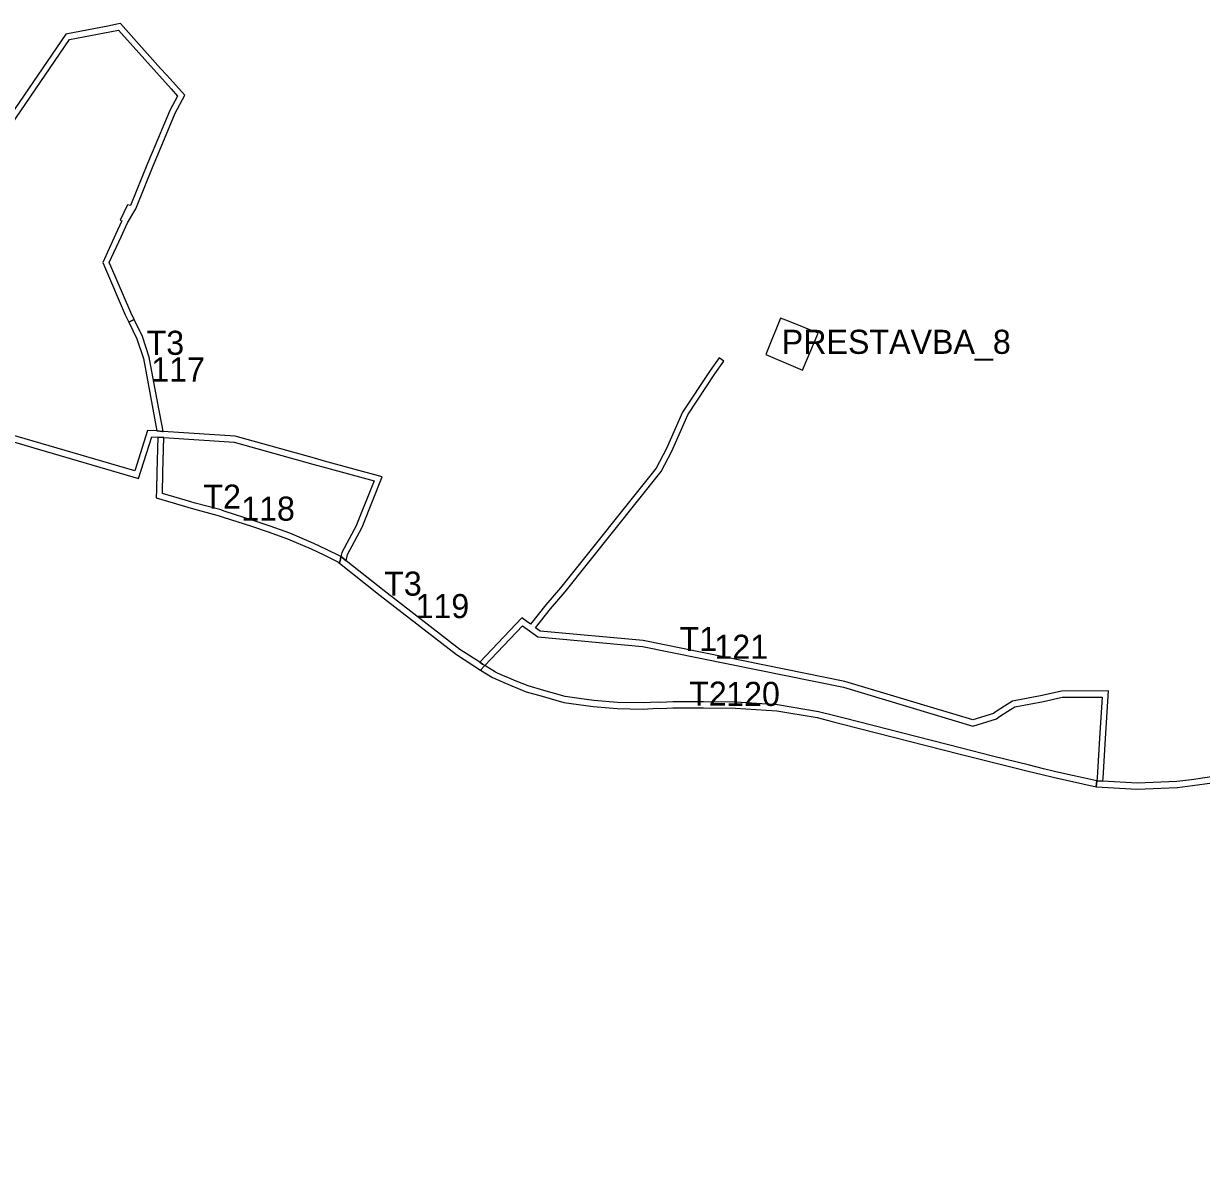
# Model space of a CAD drawing. Extents: x -477001 to -465642, y -1158278 to -1150672.
# Drawn here: x -471244 to -470657, y -1153956 to -1153393 of the extents above; entities that cross this region are included whole.
import ezdxf

# ---------------------------------------------------------------- set-up
doc = ezdxf.new("R2010")
doc.units = 0
for name, color, linetype in [('prestavba_n', 7, 'Continuous'), ('VPS_id', 7, 'Continuous'), ('VPS_n', 7, 'Continuous'), ('vyvlastneni_n', 7, 'Continuous')]:
    doc.layers.add(name, color=color, linetype=linetype)

msp = doc.modelspace()

# ---------------------------------------------------------------- linework, layer by layer
at = {"layer": 'prestavba_n'}
for p, q in [((-470866.99, -1153540.14), (-470869.35, -1153545.96)), ((-470863.08, -1153541.69), (-470866.99, -1153540.14)), ((-470848.29, -1153547.56), (-470863.08, -1153541.69)), ((-470870.6, -1153549.05), (-470874.35, -1153558.31)), ((-470869.35, -1153545.96), (-470870.6, -1153549.05)), ((-470856.01, -1153566.04), (-470848.29, -1153547.56)), ((-470874.35, -1153558.31), (-470856.01, -1153566.04))]:
    msp.add_line(p, q, dxfattribs=at)
at = {"layer": 'VPS_n'}
for p, q in [((-471192.58, -1153492.66), (-471188.38, -1153485.63)), ((-471195.38, -1153491.58), (-471198.48, -1153498.37)), ((-471195.75, -1153499.62), (-471192.58, -1153492.66)), ((-471191.89, -1153542.05), (-471189.19, -1153540.74)), ((-471189.19, -1153540.74), (-471191.89, -1153542.05)), ((-471191.89, -1153542.05), (-471187.8, -1153550.48)), ((-470895.17, -1153561.57), (-470897.61, -1153559.82)), ((-471175.31, -1153593.86), (-471176.89, -1153585.31)), ((-471182.54, -1153596.05), (-471188.94, -1153616.26)), ((-471177.9, -1153596.35), (-471175, -1153596.54)), ((-471174.82, -1153596.56), (-471175.31, -1153593.86)), ((-471175, -1153596.54), (-471174.82, -1153596.56)), ((-471180.39, -1153599.2), (-471177.37, -1153599.39)), ((-471177.37, -1153599.39), (-471174.38, -1153599.59)), ((-471174.38, -1153599.59), (-471177.37, -1153599.39)), ((-471174.96, -1153617.12), (-471174.38, -1153599.59)), ((-471174.38, -1153599.59), (-471139.38, -1153601.89)), ((-471175.11, -1153627.46), (-471174.96, -1153617.12)), ((-471178.26, -1153629.66), (-471159.57, -1153635.15)), ((-471086.84, -1153662.19), (-471086.38, -1153660.19)), ((-471086.38, -1153660.19), (-471086.84, -1153662.19)), ((-471086.38, -1153660.19), (-471086.1, -1153658.95)), ((-471086.1, -1153658.95), (-471086.38, -1153660.19)), ((-471085.63, -1153659.32), (-471086.1, -1153658.95)), ((-471083.49, -1153661.02), (-471085.63, -1153659.32)), ((-470995.98, -1153689.49), (-471016.95, -1153711.63)), ((-470991.57, -1153692.66), (-470995.98, -1153689.49)), ((-471016.95, -1153711.63), (-471026.84, -1153705.29)), ((-471016.48, -1153715.49), (-471014.38, -1153713.28)), ((-471014.38, -1153713.28), (-471016.48, -1153715.49)), ((-471009.13, -1153716.64), (-471014.38, -1153713.28)), ((-471005.94, -1153717.99), (-471009.13, -1153716.64)), ((-471003.71, -1153718.93), (-471005.94, -1153717.99)), ((-471004.87, -1153721.7), (-470993.83, -1153726.29)), ((-470984.95, -1153725.7), (-470992.84, -1153723.45)), ((-470974.36, -1153728.66), (-470984.95, -1153725.7)), ((-470948.27, -1153731.66), (-470960, -1153730.73)), ((-470926.6, -1153731.66), (-470928.14, -1153731.46)), ((-470920.74, -1153731.36), (-470926.6, -1153731.66)), ((-470889.3, -1153731.56), (-470905.33, -1153731.41)), ((-470868.42, -1153732.82), (-470889.3, -1153731.56)), ((-470967.77, -1153732.64), (-470960.33, -1153733.71)), ((-470960.33, -1153733.71), (-470948.42, -1153734.66)), ((-470948.42, -1153734.66), (-470935.44, -1153734.92)), ((-470935.44, -1153734.92), (-470928.24, -1153734.47)), ((-470928.24, -1153734.47), (-470926.72, -1153734.67)), ((-470926.72, -1153734.67), (-470920.67, -1153734.36)), ((-470920.67, -1153734.36), (-470905.35, -1153734.41)), ((-470905.35, -1153734.41), (-470889.4, -1153734.56)), ((-470889.4, -1153734.56), (-470868.76, -1153735.8)), ((-470868.76, -1153735.8), (-470848.75, -1153739.2)), ((-470848.12, -1153736.26), (-470868.42, -1153732.82)), ((-470840.51, -1153738.22), (-470848.12, -1153736.26)), ((-470835.3, -1153739.56), (-470840.51, -1153738.22)), ((-470776.74, -1153754.52), (-470835.3, -1153739.56)), ((-470761.34, -1153758.41), (-470776.74, -1153754.52)), ((-470762.07, -1153761.32), (-470743.52, -1153765.87)), ((-470742.81, -1153762.96), (-470761.34, -1153758.41)), ((-470735.83, -1153764.66), (-470742.81, -1153762.96)), ((-470730.43, -1153766.03), (-470735.83, -1153764.66)), ((-470728.24, -1153766.52), (-470730.43, -1153766.03)), ((-470709.29, -1153770.76), (-470728.24, -1153766.52)), ((-470709.71, -1153773.74), (-470709.29, -1153770.76)), ((-470709.29, -1153770.76), (-470709.71, -1153773.74)), ((-470709.29, -1153770.76), (-470706.29, -1153770.93)), ((-470706.29, -1153770.93), (-470709.29, -1153770.76)), ((-470706.29, -1153770.93), (-470706.28, -1153770.75)), ((-470689.26, -1153771.93), (-470706.29, -1153770.93)), ((-470669.37, -1153771.05), (-470689.26, -1153771.93)), ((-470662.1, -1153770.15), (-470669.37, -1153771.05)), ((-470652.22, -1153768.74), (-470662.1, -1153770.15)), ((-470709.71, -1153773.74), (-470689.28, -1153774.93)), ((-470689.28, -1153774.93), (-470669.24, -1153774.05)), ((-470669.24, -1153774.05), (-470669.12, -1153774.05))]:
    msp.add_line(p, q, dxfattribs=at)
for points in [[(-471518.29, -1153956.42), (-471540.25, -1153885.85), (-471527.35, -1153830.76), (-471528.58, -1153824.83), (-471547.09, -1153784.31), (-471550.09, -1153776.39), (-471556.65, -1153756.83), (-471579.89, -1153709.91), (-471588.26, -1153681.79), (-471591.27, -1153660.08), (-471588.75, -1153623.57), (-471590.11, -1153585.11), (-471593.12, -1153557.74), (-471592.67, -1153510.14), (-471590.89, -1153480.85), (-471590.89, -1153480.76), (-471571.76, -1153414.78), (-471284.73, -1153493.73), (-471221.49, -1153401.29), (-471197.08, -1153396.57), (-471170.8, -1153425.91), (-471167.61, -1153429.48)], [(-471163.97, -1153429.04), (-471168.57, -1153423.91), (-471171.39, -1153420.76), (-471172.87, -1153419.1), (-471175.99, -1153415.63), (-471195.98, -1153393.3), (-471197.92, -1153393.68), (-471201.53, -1153394.38), (-471223.27, -1153398.58), (-471286, -1153490.27)], [(-471167.61, -1153429.48), (-471171.44, -1153436.65), (-471180.2, -1153457.63), (-471182.49, -1153463.13), (-471190.96, -1153484.02)], [(-471188.38, -1153485.63), (-471179.72, -1153464.27), (-471177.43, -1153458.78), (-471168.73, -1153437.94), (-471163.97, -1153429.04)], [(-471190.96, -1153484.02), (-471192.48, -1153483.64), (-471196.13, -1153491.29), (-471195.38, -1153491.58)], [(-471198.48, -1153498.37), (-471204.86, -1153512.33), (-471203.51, -1153515.47), (-471193.62, -1153538.51), (-471191.89, -1153542.05)], [(-471189.19, -1153540.74), (-471190.89, -1153537.26), (-471200.75, -1153514.29), (-471201.58, -1153512.37), (-471195.75, -1153499.62)], [(-471176.89, -1153585.31), (-471181.64, -1153559.49), (-471185.02, -1153549.35), (-471189.19, -1153540.74)], [(-471187.8, -1153550.48), (-471184.55, -1153560.24), (-471177.9, -1153596.35)], [(-470897.61, -1153559.82), (-470902.14, -1153566.14), (-470915.82, -1153586.9), (-470923.8, -1153605.15), (-470929.03, -1153614.87), (-470976.69, -1153674.58), (-470983.92, -1153683.04), (-470991.57, -1153692.66)], [(-470989.12, -1153694.41), (-470981.6, -1153684.95), (-470974.38, -1153676.49), (-470926.52, -1153616.53), (-470921.1, -1153606.46), (-470913.17, -1153588.34), (-470899.67, -1153567.84), (-470895.17, -1153561.57)], [(-471188.94, -1153616.26), (-471235.56, -1153602.63), (-471306.4, -1153581.92), (-471306.81, -1153581.8), (-471330.3, -1153577.56), (-471335.95, -1153576.53), (-471341.63, -1153575.51), (-471347.71, -1153574.41), (-471374.31, -1153570.74), (-471395.17, -1153567.87), (-471395.21, -1153567.86)], [(-471395.52, -1153570.85), (-471375.15, -1153573.66), (-471348.18, -1153577.37), (-471343.75, -1153578.17), (-471337.99, -1153579.22), (-471332.35, -1153580.23), (-471312.85, -1153583.76), (-471307.5, -1153584.72), (-471236.4, -1153605.51), (-471186.96, -1153619.97), (-471180.39, -1153599.2)], [(-471083.49, -1153661.02), (-471082.8, -1153657.97), (-471075.7, -1153644.56), (-471075.27, -1153643.48), (-471065.56, -1153619.23), (-471094.33, -1153611.37), (-471099.33, -1153609.95), (-471138.87, -1153598.92), (-471174.82, -1153596.56), (-471175, -1153596.54), (-471177.9, -1153596.35), (-471182.54, -1153596.05)], [(-471177.37, -1153599.39), (-471177.96, -1153617.05), (-471178.08, -1153625.46), (-471178.26, -1153629.66)], [(-471139.38, -1153601.89), (-471100.14, -1153612.84), (-471095.14, -1153614.26), (-471069.6, -1153621.24), (-471078.06, -1153642.37), (-471078.43, -1153643.3), (-471085.64, -1153656.92), (-471086.1, -1153658.95)], [(-471086.1, -1153658.95), (-471093.38, -1153655.43), (-471099.64, -1153652.41), (-471111.66, -1153647.23), (-471121.43, -1153643.85), (-471129.85, -1153640.93), (-471143.86, -1153636.43), (-471146.55, -1153635.57), (-471147.12, -1153635.39), (-471158.75, -1153632.26), (-471161, -1153631.6), (-471175.11, -1153627.46)], [(-471159.57, -1153635.15), (-471147.97, -1153638.27), (-471147.4, -1153638.45), (-471144.79, -1153639.28), (-471130.7, -1153643.81), (-471122.39, -1153646.69), (-471112.75, -1153650.03), (-471100.89, -1153655.14), (-471094.68, -1153658.13), (-471087.7, -1153661.51), (-471087.49, -1153661.67), (-471086.84, -1153662.19)], [(-471086.1, -1153658.95), (-471085.63, -1153659.32), (-471083.49, -1153661.02)], [(-471026.84, -1153705.29), (-471064.65, -1153676), (-471083.49, -1153661.02)], [(-471086.84, -1153662.19), (-471066.5, -1153678.36), (-471028.57, -1153707.74), (-471016.48, -1153715.49)], [(-471014.38, -1153713.28), (-470995.61, -1153693.45), (-470987.91, -1153698.97), (-470935.86, -1153703.7), (-470835.66, -1153724.06), (-470771.19, -1153743.46), (-470759.35, -1153739.79), (-470757.77, -1153738.6), (-470753.7, -1153736.05), (-470750.24, -1153733.9), (-470735.9, -1153731.18), (-470726.65, -1153729.03), (-470706.64, -1153728.95), (-470708.06, -1153749.43), (-470709.2, -1153769.21), (-470709.29, -1153770.76)], [(-470706.28, -1153770.75), (-470706.21, -1153769.38), (-470705.07, -1153749.62), (-470703.42, -1153725.94), (-470727, -1153726.03), (-470736.52, -1153728.24), (-470751.35, -1153731.06), (-470755.29, -1153733.5), (-470759.47, -1153736.13), (-470760.74, -1153737.08), (-470771.2, -1153740.32), (-470834.93, -1153721.15), (-470935.43, -1153700.73), (-470986.82, -1153696.05), (-470989.12, -1153694.41)], [(-471014.38, -1153713.28), (-471015.59, -1153712.5), (-471016.95, -1153711.63)], [(-471016.95, -1153711.63), (-471015.59, -1153712.5), (-471014.38, -1153713.28)], [(-471016.48, -1153715.49), (-471010.53, -1153719.3), (-471007.11, -1153720.75), (-471004.87, -1153721.7)], [(-470992.84, -1153723.45), (-470998.78, -1153720.98), (-471003.71, -1153718.93)], [(-470993.83, -1153726.29), (-470985.77, -1153728.59), (-470974.98, -1153731.6), (-470967.77, -1153732.64)], [(-470960, -1153730.73), (-470967.34, -1153729.67), (-470974.36, -1153728.66)], [(-470928.14, -1153731.46), (-470935.5, -1153731.92), (-470948.27, -1153731.66)], [(-470905.33, -1153731.41), (-470907.23, -1153731.39), (-470920.74, -1153731.36)], [(-470848.75, -1153739.2), (-470841.26, -1153741.13), (-470836.04, -1153742.47), (-470777.48, -1153757.43), (-470762.07, -1153761.32)], [(-470743.52, -1153765.87), (-470736.55, -1153767.57), (-470731.13, -1153768.95), (-470709.71, -1153773.74)], [(-470669.12, -1153774.05), (-470661.7, -1153773.12), (-470651.8, -1153771.71), (-470641.9, -1153770.29), (-470631.99, -1153768.97), (-470622.04, -1153767.97), (-470612.27, -1153767.24)]]:
    msp.add_lwpolyline(points, dxfattribs=at)
at = {"layer": 'vyvlastneni_n'}
for p, q in [((-471192.58, -1153492.66), (-471188.38, -1153485.63)), ((-471195.38, -1153491.58), (-471198.48, -1153498.37)), ((-471195.75, -1153499.62), (-471192.58, -1153492.66)), ((-471191.89, -1153542.05), (-471189.19, -1153540.74)), ((-471189.19, -1153540.74), (-471191.89, -1153542.05)), ((-471191.89, -1153542.05), (-471187.8, -1153550.48)), ((-470895.17, -1153561.57), (-470897.61, -1153559.82)), ((-471175.31, -1153593.86), (-471176.89, -1153585.31)), ((-471182.54, -1153596.05), (-471188.94, -1153616.26)), ((-471177.9, -1153596.35), (-471175, -1153596.54)), ((-471174.82, -1153596.56), (-471175.31, -1153593.86)), ((-471175, -1153596.54), (-471174.82, -1153596.56)), ((-471180.39, -1153599.2), (-471177.37, -1153599.39)), ((-471177.37, -1153599.39), (-471174.38, -1153599.59)), ((-471174.38, -1153599.59), (-471177.37, -1153599.39)), ((-471174.96, -1153617.12), (-471174.38, -1153599.59)), ((-471174.38, -1153599.59), (-471139.38, -1153601.89)), ((-471175.11, -1153627.46), (-471174.96, -1153617.12)), ((-471178.26, -1153629.66), (-471159.57, -1153635.15)), ((-471086.84, -1153662.19), (-471086.38, -1153660.19)), ((-471086.38, -1153660.19), (-471086.84, -1153662.19)), ((-471086.38, -1153660.19), (-471086.1, -1153658.95)), ((-471086.1, -1153658.95), (-471086.38, -1153660.19)), ((-471085.63, -1153659.32), (-471086.1, -1153658.95)), ((-471083.49, -1153661.02), (-471085.63, -1153659.32)), ((-470995.98, -1153689.49), (-471016.95, -1153711.63)), ((-470991.57, -1153692.66), (-470995.98, -1153689.49)), ((-471016.95, -1153711.63), (-471026.84, -1153705.29)), ((-471016.48, -1153715.49), (-471014.38, -1153713.28)), ((-471014.38, -1153713.28), (-471016.48, -1153715.49)), ((-471009.13, -1153716.64), (-471014.38, -1153713.28)), ((-471005.94, -1153717.99), (-471009.13, -1153716.64)), ((-471003.71, -1153718.93), (-471005.94, -1153717.99)), ((-471004.87, -1153721.7), (-470993.83, -1153726.29)), ((-470984.95, -1153725.7), (-470992.84, -1153723.45)), ((-470974.36, -1153728.66), (-470984.95, -1153725.7)), ((-470948.27, -1153731.66), (-470960, -1153730.73)), ((-470926.6, -1153731.66), (-470928.14, -1153731.46)), ((-470920.74, -1153731.36), (-470926.6, -1153731.66)), ((-470889.3, -1153731.56), (-470905.33, -1153731.41)), ((-470868.42, -1153732.82), (-470889.3, -1153731.56)), ((-470967.77, -1153732.64), (-470960.33, -1153733.71)), ((-470960.33, -1153733.71), (-470948.42, -1153734.66)), ((-470948.42, -1153734.66), (-470935.44, -1153734.92)), ((-470935.44, -1153734.92), (-470928.24, -1153734.47)), ((-470928.24, -1153734.47), (-470926.72, -1153734.67)), ((-470926.72, -1153734.67), (-470920.67, -1153734.36)), ((-470920.67, -1153734.36), (-470905.35, -1153734.41)), ((-470905.35, -1153734.41), (-470889.4, -1153734.56)), ((-470889.4, -1153734.56), (-470868.76, -1153735.8)), ((-470868.76, -1153735.8), (-470848.75, -1153739.2)), ((-470848.12, -1153736.26), (-470868.42, -1153732.82)), ((-470840.51, -1153738.22), (-470848.12, -1153736.26)), ((-470835.3, -1153739.56), (-470840.51, -1153738.22)), ((-470776.74, -1153754.52), (-470835.3, -1153739.56)), ((-470761.34, -1153758.41), (-470776.74, -1153754.52)), ((-470762.07, -1153761.32), (-470743.52, -1153765.87)), ((-470742.81, -1153762.96), (-470761.34, -1153758.41)), ((-470735.83, -1153764.66), (-470742.81, -1153762.96)), ((-470730.43, -1153766.03), (-470735.83, -1153764.66)), ((-470728.24, -1153766.52), (-470730.43, -1153766.03)), ((-470709.29, -1153770.76), (-470728.24, -1153766.52)), ((-470709.71, -1153773.74), (-470709.29, -1153770.76)), ((-470709.29, -1153770.76), (-470709.71, -1153773.74)), ((-470709.29, -1153770.76), (-470706.29, -1153770.93)), ((-470706.29, -1153770.93), (-470709.29, -1153770.76)), ((-470706.29, -1153770.93), (-470706.28, -1153770.75)), ((-470689.26, -1153771.93), (-470706.29, -1153770.93)), ((-470669.37, -1153771.05), (-470689.26, -1153771.93)), ((-470662.1, -1153770.15), (-470669.37, -1153771.05)), ((-470652.22, -1153768.74), (-470662.1, -1153770.15)), ((-470709.71, -1153773.74), (-470689.28, -1153774.93)), ((-470689.28, -1153774.93), (-470669.24, -1153774.05)), ((-470669.24, -1153774.05), (-470669.12, -1153774.05))]:
    msp.add_line(p, q, dxfattribs=at)
for points in [[(-471518.29, -1153956.42), (-471540.25, -1153885.85), (-471527.35, -1153830.76), (-471528.58, -1153824.83), (-471547.09, -1153784.31), (-471550.09, -1153776.39), (-471556.65, -1153756.83), (-471579.89, -1153709.91), (-471588.26, -1153681.79), (-471591.27, -1153660.08), (-471588.75, -1153623.57), (-471590.11, -1153585.11), (-471593.12, -1153557.74), (-471592.67, -1153510.14), (-471590.89, -1153480.85), (-471590.89, -1153480.76), (-471571.76, -1153414.78), (-471284.73, -1153493.73), (-471221.49, -1153401.29), (-471197.08, -1153396.57), (-471170.8, -1153425.91), (-471167.61, -1153429.48)], [(-471163.97, -1153429.04), (-471168.57, -1153423.91), (-471171.39, -1153420.76), (-471172.87, -1153419.1), (-471175.99, -1153415.63), (-471195.98, -1153393.3), (-471197.92, -1153393.68), (-471201.53, -1153394.38), (-471223.27, -1153398.58), (-471286, -1153490.27)], [(-471167.61, -1153429.48), (-471171.44, -1153436.65), (-471180.2, -1153457.63), (-471182.49, -1153463.13), (-471190.96, -1153484.02)], [(-471188.38, -1153485.63), (-471179.72, -1153464.27), (-471177.43, -1153458.78), (-471168.73, -1153437.94), (-471163.97, -1153429.04)], [(-471190.96, -1153484.02), (-471192.48, -1153483.64), (-471196.13, -1153491.29), (-471195.38, -1153491.58)], [(-471198.48, -1153498.37), (-471204.86, -1153512.33), (-471203.51, -1153515.47), (-471193.62, -1153538.51), (-471191.89, -1153542.05)], [(-471189.19, -1153540.74), (-471190.89, -1153537.26), (-471200.75, -1153514.29), (-471201.58, -1153512.37), (-471195.75, -1153499.62)], [(-471176.89, -1153585.31), (-471181.64, -1153559.49), (-471185.02, -1153549.35), (-471189.19, -1153540.74)], [(-471187.8, -1153550.48), (-471184.55, -1153560.24), (-471177.9, -1153596.35)], [(-470897.61, -1153559.82), (-470902.14, -1153566.14), (-470915.82, -1153586.9), (-470923.8, -1153605.15), (-470929.03, -1153614.87), (-470976.69, -1153674.58), (-470983.92, -1153683.04), (-470991.57, -1153692.66)], [(-470989.12, -1153694.41), (-470981.6, -1153684.95), (-470974.38, -1153676.49), (-470926.52, -1153616.53), (-470921.1, -1153606.46), (-470913.17, -1153588.34), (-470899.67, -1153567.84), (-470895.17, -1153561.57)], [(-471188.94, -1153616.26), (-471235.56, -1153602.63), (-471306.4, -1153581.92), (-471306.81, -1153581.8), (-471330.3, -1153577.56), (-471335.95, -1153576.53), (-471341.63, -1153575.51), (-471347.71, -1153574.41), (-471374.31, -1153570.74), (-471395.17, -1153567.87), (-471395.21, -1153567.86)], [(-471395.52, -1153570.85), (-471375.15, -1153573.66), (-471348.18, -1153577.37), (-471343.75, -1153578.17), (-471337.99, -1153579.22), (-471332.35, -1153580.23), (-471312.85, -1153583.76), (-471307.5, -1153584.72), (-471236.4, -1153605.51), (-471186.96, -1153619.97), (-471180.39, -1153599.2)], [(-471083.49, -1153661.02), (-471082.8, -1153657.97), (-471075.7, -1153644.56), (-471075.27, -1153643.48), (-471065.56, -1153619.23), (-471094.33, -1153611.37), (-471099.33, -1153609.95), (-471138.87, -1153598.92), (-471174.82, -1153596.56), (-471175, -1153596.54), (-471177.9, -1153596.35), (-471182.54, -1153596.05)], [(-471177.37, -1153599.39), (-471177.96, -1153617.05), (-471178.08, -1153625.46), (-471178.26, -1153629.66)], [(-471139.38, -1153601.89), (-471100.14, -1153612.84), (-471095.14, -1153614.26), (-471069.6, -1153621.24), (-471078.06, -1153642.37), (-471078.43, -1153643.3), (-471085.64, -1153656.92), (-471086.1, -1153658.95)], [(-471086.1, -1153658.95), (-471093.38, -1153655.43), (-471099.64, -1153652.41), (-471111.66, -1153647.23), (-471121.43, -1153643.85), (-471129.85, -1153640.93), (-471143.86, -1153636.43), (-471146.55, -1153635.57), (-471147.12, -1153635.39), (-471158.75, -1153632.26), (-471161, -1153631.6), (-471175.11, -1153627.46)], [(-471159.57, -1153635.15), (-471147.97, -1153638.27), (-471147.4, -1153638.45), (-471144.79, -1153639.28), (-471130.7, -1153643.81), (-471122.39, -1153646.69), (-471112.75, -1153650.03), (-471100.89, -1153655.14), (-471094.68, -1153658.13), (-471087.7, -1153661.51), (-471087.49, -1153661.67), (-471086.84, -1153662.19)], [(-471086.1, -1153658.95), (-471085.63, -1153659.32), (-471083.49, -1153661.02)], [(-471026.84, -1153705.29), (-471064.65, -1153676), (-471083.49, -1153661.02)], [(-471086.84, -1153662.19), (-471066.5, -1153678.36), (-471028.57, -1153707.74), (-471016.48, -1153715.49)], [(-471014.38, -1153713.28), (-470995.61, -1153693.45), (-470987.91, -1153698.97), (-470935.86, -1153703.7), (-470835.66, -1153724.06), (-470771.19, -1153743.46), (-470759.35, -1153739.79), (-470757.77, -1153738.6), (-470753.7, -1153736.05), (-470750.24, -1153733.9), (-470735.9, -1153731.18), (-470726.65, -1153729.03), (-470706.64, -1153728.95), (-470708.06, -1153749.43), (-470709.2, -1153769.21), (-470709.29, -1153770.76)], [(-470706.28, -1153770.75), (-470706.21, -1153769.38), (-470705.07, -1153749.62), (-470703.42, -1153725.94), (-470727, -1153726.03), (-470736.52, -1153728.24), (-470751.35, -1153731.06), (-470755.29, -1153733.5), (-470759.47, -1153736.13), (-470760.74, -1153737.08), (-470771.2, -1153740.32), (-470834.93, -1153721.15), (-470935.43, -1153700.73), (-470986.82, -1153696.05), (-470989.12, -1153694.41)], [(-471014.38, -1153713.28), (-471015.59, -1153712.5), (-471016.95, -1153711.63)], [(-471016.95, -1153711.63), (-471015.59, -1153712.5), (-471014.38, -1153713.28)], [(-471016.48, -1153715.49), (-471010.53, -1153719.3), (-471007.11, -1153720.75), (-471004.87, -1153721.7)], [(-470992.84, -1153723.45), (-470998.78, -1153720.98), (-471003.71, -1153718.93)], [(-470993.83, -1153726.29), (-470985.77, -1153728.59), (-470974.98, -1153731.6), (-470967.77, -1153732.64)], [(-470960, -1153730.73), (-470967.34, -1153729.67), (-470974.36, -1153728.66)], [(-470928.14, -1153731.46), (-470935.5, -1153731.92), (-470948.27, -1153731.66)], [(-470905.33, -1153731.41), (-470907.23, -1153731.39), (-470920.74, -1153731.36)], [(-470848.75, -1153739.2), (-470841.26, -1153741.13), (-470836.04, -1153742.47), (-470777.48, -1153757.43), (-470762.07, -1153761.32)], [(-470743.52, -1153765.87), (-470736.55, -1153767.57), (-470731.13, -1153768.95), (-470709.71, -1153773.74)], [(-470669.12, -1153774.05), (-470661.7, -1153773.12), (-470651.8, -1153771.71), (-470641.9, -1153770.29), (-470631.99, -1153768.97), (-470622.04, -1153767.97), (-470612.27, -1153767.24)]]:
    msp.add_lwpolyline(points, dxfattribs=at)

# ---------------------------------------------------------------- texts
at = {"layer": 'prestavba_n'}
msp.add_text('PRESTAVBA_8', height=12, dxfattribs=at).set_placement((-470866.37, -1153557.92))
at = {"layer": 'VPS_id'}
for s, p in [('117', (-471180.7, -1153571.71)), ('118', (-471135.84, -1153641.07)), ('119', (-471048.95, -1153689.63)), ('121', (-470899.95, -1153709.9)), ('120', (-470894.09, -1153733.39))]:
    msp.add_text(s, height=12, dxfattribs=at).set_placement(p)
at = {"layer": 'VPS_n'}
for s, p in [('T3', (-471183.01, -1153558.41)), ('T2', (-471154.69, -1153635.07)), ('T3', (-471064.58, -1153678.44)), ('T1', (-470917.33, -1153705.98)), ('T2', (-470912.51, -1153733.27))]:
    msp.add_text(s, height=12, dxfattribs=at).set_placement(p)

doc.saveas('drawing.dxf')
